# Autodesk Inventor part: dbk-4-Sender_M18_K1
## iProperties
Shininess: 20.0
Length Units: 11269
Angle Units: 11279
Time Units: 11290
Mass Units: 11283
Length Display Precision: 2
Angle Display Precision: 2
Part Number: dbk-4-Sender_M18_K1
Material: Nichtrostender Stahl - 440C
Document SubType Name: Modellieren
Description: dbk-4/Sender/M18/K2
Checked By: Alves
Created: 2005-08
Designer: Ohle
Manufacturer: Standard
Standards Organization: Custom
Density: 0.0
Volumn: 0.0
Area: 0.0
PropertySet Name: Model Information
Control State: 0
Master: False
Checked Out: False
Last Check In By: Kramp
Last Check In Date: 2005-08-10
BESTELLNUMMER: dbk-4/Sender/M18/K1
ME: ST
Title: dbk-4 Sensoren
Author: Ohle
Comments: keine Bemerkung
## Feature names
1. dbk-4 Sender [Revolution]
2. Extrusion6
3. Extrusion7
